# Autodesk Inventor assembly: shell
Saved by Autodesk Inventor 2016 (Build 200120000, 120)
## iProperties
Created: 2018-05
Part Number: shell
Document SubType Name: Assembly
Designer: Administrator
Title: shell
Author: Administrator
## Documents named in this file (4)
- c:\worker\convert-fusion-mar-2018\tmp\job-1\16\output\files\8c58ff39-88bb-4352-afd9-60265520bae5\shell.iam
- c:\worker\convert-fusion-mar-2018\tmp\job-1\16\output\files\8c58ff39-88bb-4352-afd9-60265520bae5\outer.ipt
- c:\worker\convert-fusion-mar-2018\tmp\job-1\16\output\files\8c58ff39-88bb-4352-afd9-60265520bae5\back_shell.ipt
- c:\worker\convert-fusion-mar-2018\tmp\job-1\16\output\files\8c58ff39-88bb-4352-afd9-60265520bae5\mid_cover.ipt
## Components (3 placed, 3 different names)
1. outer:1
2. back_shell:1
3. mid_cover:1
